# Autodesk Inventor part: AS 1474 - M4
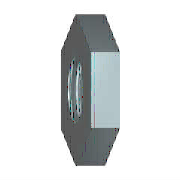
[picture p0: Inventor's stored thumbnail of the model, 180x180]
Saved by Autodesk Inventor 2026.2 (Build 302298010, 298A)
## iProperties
Created: 2025-01
Part Number: AS 1474 - M4
Material: 강철, 연강
Description: 6각 너트
Document SubType Name: Modeling
Standard: AS 1474
Designer: work
Standards Organization: AS
Language: ko-KR
Size Designation: M4
Categories: <MemberInstance><Categories><Category DisplayName="조임쇠" InternalName="e4da775c-781d-43d5-af7c-5136215cf5a6" Mnemonic="FSTN"><Category DisplayName="너트" InternalN
Density: 7.85 g/cm^3
Appearance: 반연마
IsCustomPart: 1
Author: work
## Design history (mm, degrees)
body "Solid1"
sketch "스케치1"
  geometry: L1 (2.021, -3.5)-(-2.021, -3.5); L2 (-2.021, -3.5)-(-4.041, 0); L3 (-4.041, 0)-(-2.021, 3.5); L4 (-2.021, 3.5)-(2.021, 3.5); L5 (2.021, 3.5)-(4.041, 0); L6 (4.041, 0)-(2.021, -3.5); 2 further points
  constraints: 12 end point, 1 coincident, 1 horizontal, 11 other
  dimensions: "d0" = 8.0829 distance of L5.end L2.end (= 1.1547 x SW)
extrude "본체" new body sketch "스케치1" distance "d1" = 2.2 (= KOH); taper "d2" = 0 deg
sketch "스케치2"
  geometry: 1 further point
hole "스레드" sketch "스케치2" diameter "d3" = 3.242; stored, may be unused: countersink angle "d7" = 82 deg, drill point angle "d9" = 118 deg; dims "d4" = 6, "d5" = 4, "d6" = 2, "d8" = 8
workaxis "Work Axis1"
workplane "Work Plane1"
chamfer "모따기2" distance "d12" = 0.37889 (= -0.5 x GD1 + 0.5 x NND); stored, may be unused: angle "d13" = 30 deg, second distance "d19" = 0.37889 (= -0.5 x GD1 + 0.5 x NND)
chamfer "모따기1" distance "d10" = 0.37889 (= -0.5 x GD1 + 0.5 x NND); stored, may be unused: angle "d11" = 30 deg, second distance "d18" = 0.37889 (= -0.5 x GD1 + 0.5 x NND)
other parameters: "NND" = 4 [user parameter; used in 4 equation terms], "KOH" = 2.2 [user parameter; used in 1 equation term], "SW" = 7 [user parameter; used in 2 equation terms], "GD1" = 3.24223 (computed from THREADDIA, PTC, TOA) [user parameter; used in 4 equation terms], "d15" = 0, "d17" = 0, "d20" = 0, "d21" = 0, "GUL" = 0.37889 (= 0.541266 x PTC) [user parameter], "TPU" = 14.28571 (computed from PTC) [user parameter], "THREADDIA" = 4 [user parameter; used in 1 equation term], "TOA" = 30 deg [user parameter; used in 1 equation term], "PTC" = 0.7 [user parameter; used in 4 equation terms], "E0" = 8.085 (= 1.155 x SW) [user parameter], "GAL" = 0.37889 (= 0.541266 x PTC) [user parameter]
